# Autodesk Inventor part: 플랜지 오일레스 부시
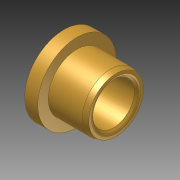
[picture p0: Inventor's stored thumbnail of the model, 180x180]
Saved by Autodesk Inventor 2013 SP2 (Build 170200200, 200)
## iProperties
Created: 2025-04
Part Number: 플랜지 오일레스 부시
Material: Generic
Document SubType Name: Modeling
Designer: 601
Density: 1 g/cm^3
Author: 601
변환 표준: STEP AP214IS
전처리기: Build: 200, Release: 2013 SP2 Update 6 - Date: Thu 07/17/2014
전송 단위: 밀리미터
불확실성: 0.01
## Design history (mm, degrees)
node "플랜지 오일레스 부시1"
node "솔리드1"
node "기준1"
